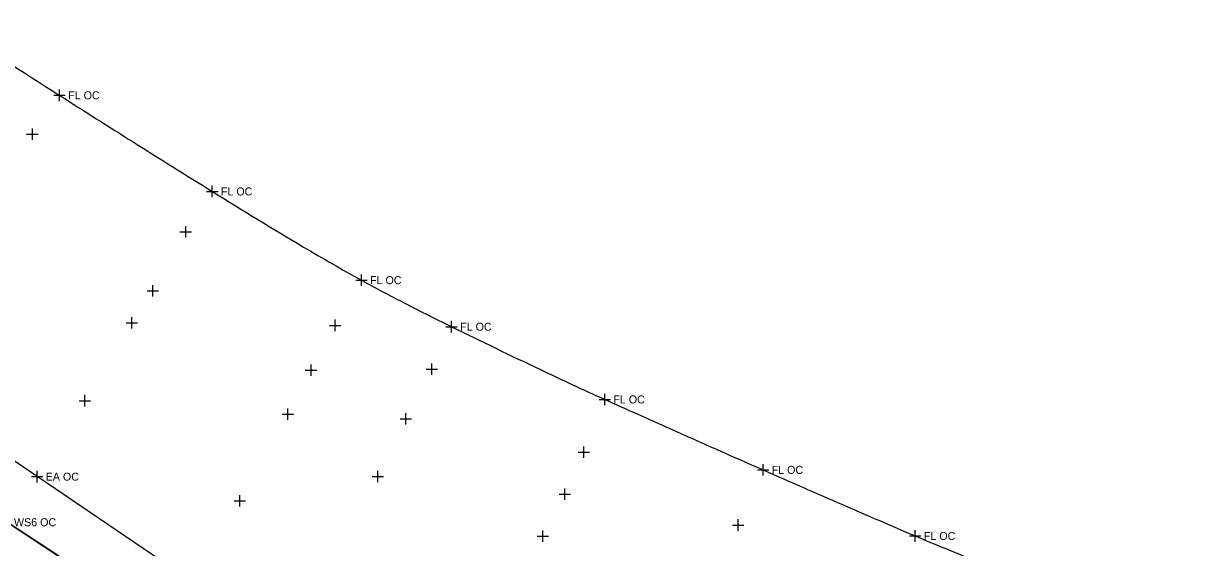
# Model space of a CAD drawing. Extents: x 1324236 to 1326110, y 459090 to 460782.
# Drawn here: x 1324542.9 to 1324746, y 460621.6 to 460713.3 of the extents above; entities that cross this region are included whole.
import ezdxf

# ---------------------------------------------------------------- set-up
doc = ezdxf.new("R2010")
doc.units = 0
for name, color, linetype in [('DR_X_Ditch', 7, 'Continuous'), ('DV_X_Property_Line', 7, 'Continuous'), ('PM_X_CL_Double_Solid', 7, 'Continuous'), ('PM_X_Edge_Line', 7, 'Continuous'), ('PV_X_Shoulder', 7, 'Continuous'), ('RW_X_CL', 7, 'Continuous'), ('RW_X_Esmt_SH', 7, 'Continuous')]:
    doc.layers.add(name, color=color, linetype=linetype)

msp = doc.modelspace()

# ---------------------------------------------------------------- linework, layer by layer
at = {"layer": 'DR_X_Ditch'}
msp.add_lwpolyline([(1324552.81, 460617.74), (1324540.09, 460626.06)], dxfattribs=at)
at = {"layer": 'DV_X_Property_Line'}
for p, q in [((1324545.31, 460633.03), (1324545.31, 460635.03)), ((1324544.31, 460634.03), (1324546.31, 460634.03))]:
    msp.add_line(p, q, dxfattribs=at)
at = {"layer": 'PM_X_CL_Double_Solid'}
for centre, radius, start, end in [((1326215.73, 463321.45), 3105.72, 237.11748, 237.54836), ((1326255.06, 463383.31), 3179.03, 237.54836, 237.8231), ((1326503.46, 463778.12), 3645.48, 237.8231, 238.07967), ((1325051.57, 461447.39), 899.52, 238.07967, 239.2694), ((1324771.42, 460976.14), 351.28, 239.2694, 241.1733), ((1324744.2, 460926.68), 294.83, 241.1733, 242.6748), ((1324836.3, 461104.95), 495.48, 242.6748, 243.833), ((1325167.27, 461778.53), 1245.98, 243.83296, 244.62625), ((1324908.9, 461233.76), 643.05, 244.62625, 245.73051), ((1325656.04, 462890.85), 2460.78, 245.73051, 246.0215), ((1326687.8, 465210.57), 4999.62, 246.0215, 246.22566), ((1325843.38, 463293.68), 2904.98, 246.22566, 246.52436), ((1325658.03, 462866.9), 2439.68, 246.52436, 246.8503), ((1324842.82, 460960.27), 366.08, 246.8503, 248.6567)]:
    msp.add_arc(centre, radius, start, end, dxfattribs=at)
at = {"layer": 'PM_X_Edge_Line'}
msp.add_arc((1324943.63, 461229.32), 725.79, 236.22039, 237.41995, dxfattribs=at)
at = {"layer": 'PV_X_Shoulder'}
msp.add_lwpolyline([(1324892.37, 460493.49), (1324860.6, 460503.39), (1324828.49, 460513.21), (1324798.71, 460522.26), (1324777.87, 460528.9), (1324767.13, 460532.33), (1324737.7, 460541.77), (1324736.57, 460542.13), (1324724.28, 460546.18), (1324705.87, 460552.49), (1324692.5, 460557.36), (1324676.12, 460563.81), (1324663.42, 460569.15), (1324646.7, 460576.57), (1324628.95, 460584.84), (1324618.08, 460590.25), (1324607.15, 460596.07), (1324589.72, 460605.76), (1324574.73, 460614.33), (1324571.84, 460616.11), (1324566.97, 460619.36), (1324545.31, 460634.03), (1324520.36, 460651)], dxfattribs=at)
at = {"layer": 'RW_X_CL'}
for p, q in [((1324543.48, 460693.92), (1324545.48, 460693.92)), ((1324544.48, 460692.92), (1324544.48, 460694.92)), ((1324571.3, 460675.83), (1324571.3, 460677.83)), ((1324570.3, 460676.83), (1324572.3, 460676.83)), ((1324565.56, 460665.54), (1324565.56, 460667.54)), ((1324564.56, 460666.54), (1324566.56, 460666.54)), ((1324561.86, 460659.91), (1324561.86, 460661.91)), ((1324597.45, 460659.49), (1324597.45, 460661.49)), ((1324560.86, 460660.91), (1324562.86, 460660.91)), ((1324596.45, 460660.49), (1324598.45, 460660.49)), ((1324593.22, 460651.65), (1324593.22, 460653.65)), ((1324613.33, 460652.84), (1324615.33, 460652.84)), ((1324614.33, 460651.84), (1324614.33, 460653.84)), ((1324592.22, 460652.65), (1324594.22, 460652.65)), ((1324552.67, 460647.31), (1324554.67, 460647.31)), ((1324553.67, 460646.31), (1324553.67, 460648.31)), ((1324588.17, 460644.97), (1324590.17, 460644.97)), ((1324589.17, 460643.97), (1324589.17, 460645.97)), ((1324609.8, 460643.16), (1324609.8, 460645.16)), ((1324608.8, 460644.16), (1324610.8, 460644.16)), ((1324640.93, 460637.33), (1324640.93, 460639.33)), ((1324639.93, 460638.33), (1324641.93, 460638.33)), ((1324604.9, 460633.06), (1324604.9, 460635.06)), ((1324603.9, 460634.06), (1324605.9, 460634.06)), ((1324580.76, 460628.79), (1324580.76, 460630.79)), ((1324636.6, 460630.94), (1324638.6, 460630.94)), ((1324637.6, 460629.95), (1324637.6, 460631.95)), ((1324579.76, 460629.79), (1324581.76, 460629.79)), ((1324667.94, 460624.57), (1324667.94, 460626.57)), ((1324633.77, 460622.63), (1324633.77, 460624.63)), ((1324666.94, 460625.57), (1324668.94, 460625.57)), ((1324632.77, 460623.63), (1324634.77, 460623.63))]:
    msp.add_line(p, q, dxfattribs=at)
at = {"layer": 'RW_X_Esmt_SH'}
for p, q in [((1324549.24, 460699.71), (1324549.24, 460701.71)), ((1324548.24, 460700.71), (1324550.24, 460700.71)), ((1324574.95, 460683.9), (1324576.95, 460683.9)), ((1324575.95, 460682.9), (1324575.95, 460684.9)), ((1324602.04, 460667.39), (1324602.04, 460669.39)), ((1324601.04, 460668.39), (1324603.04, 460668.39)), ((1324617.8, 460659.25), (1324617.8, 460661.25)), ((1324616.8, 460660.25), (1324618.8, 460660.25)), ((1324643.59, 460647.54), (1324645.59, 460647.54)), ((1324644.59, 460646.54), (1324644.59, 460648.54)), ((1324671.28, 460635.22), (1324673.28, 460635.22)), ((1324672.28, 460634.22), (1324672.28, 460636.22)), ((1324698.9, 460622.66), (1324698.9, 460624.66)), ((1324697.9, 460623.66), (1324699.9, 460623.66))]:
    msp.add_line(p, q, dxfattribs=at)

# ---------------------------------------------------------------- texts
at = {"layer": 'DV_X_Property_Line'}
msp.add_text('EA OC', height=1.4, dxfattribs=at).set_placement((1324546.81, 460633.33))
at = {"layer": 'RW_X_CL'}
msp.add_text('WS6 OC', height=1.4, dxfattribs=at).set_placement((1324541.26, 460625.36))
at = {"layer": 'RW_X_Esmt_SH'}
for p in [(1324550.74, 460700.01), (1324577.45, 460683.2), (1324603.54, 460667.69), (1324619.3, 460659.55), (1324646.09, 460646.84), (1324673.78, 460634.52), (1324700.4, 460622.96)]:
    msp.add_text('FL OC', height=1.4, dxfattribs=at).set_placement(p)

doc.saveas('drawing.dxf')
